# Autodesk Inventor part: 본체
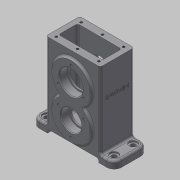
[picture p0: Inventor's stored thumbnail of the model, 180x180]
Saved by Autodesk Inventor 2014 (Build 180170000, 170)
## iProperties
Created: 2020-03
Part Number: 본체
Material: 일반
Document SubType Name: Modeling
Designer: mduedu
Density: 1 g/cm^3
Appearance: 기본값
Author: mduedu
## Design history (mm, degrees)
sketch "스케치1"
  geometry: L1 (-56, 0)-(56, 0); L2 (56, 0)-(56, 10); L3 (-56, 10)-(-56, 0); L4 (37, 10)-(37, 114); L5 (37, 114)-(-37, 114); L6 (-37, 114)-(-37, 10); L7 (56, 10)-(37, 10); L8 (-37, 10)-(-56, 10); L9 (0, 0)-(0, 114); 1 further point
  constraints: 18 end point, 5 parallel, 2 midpoint, 2 vertical, 1 coincident, 1 horizontal, 1 perpendicular
  dimensions: "d0" = 112 distance of L1.start L1.end; "d2" = 10 distance of L1.end L2.end; "d3" = 114 distance between parallel lines of L5 L1; "d4" = 74 distance between parallel lines of L4 L6
extrude "돌출1" new body sketch "스케치1" stored distance "d5" = 46; taper "d6" = 0 deg
sketch "스케치2"
  geometry: L1 (56, 0)-(-56, 0) reference; C1 r 26 at (0, 34); C2 r 26 at (0, 79); 1 further point
  constraints: 2 centre point, 2 vertical alignment, 1 equal radius
  dimensions: "d7" = 52 diameter of C2; "d9" = 34 distance from line of C1.centre L1; "d10" = 45 distance of C2.centre C1.centre
extrude "돌출2" join sketch "스케치2" stored distance "d11" = 52; taper "d12" = 0 deg
fillet "모깎기1" dims "d13" = 3
fillet "모깎기2" dims "d14" = 3
fillet "모깎기3" dims "d15" = 10
fillet "모깎기4" dims "d16" = 3
fillet "모깎기5" dims "d17" = 3
sketch "스케치3"
  geometry: L1 (-30, 114)-(30, 114); L2 (30, 114)-(30, 13); L3 (30, 13)-(-30, 13); L4 (-30, 13)-(-30, 114); L5 (-34, 114)-(34, 114) reference; L6 (46, 0)-(-46, 0) reference; 2 further points
  constraints: 8 end point, 2 parallel, 1 collinear, 1 horizontal, 1 midpoint, 1 perpendicular, 1 vertical alignment
  dimensions: "d18" = 60 distance between parallel lines of L2 L4; "d20" = 13 distance between parallel lines of L3 L6
extrude "돌출3" cut sketch "스케치3" stored distance "d21" = 26; taper "d22" = 0 deg
fillet "모깎기6" dims "d23" = 3
fillet "모깎기7" dims "d24" = 3
sketch "스케치4"
  geometry: L1 (-35, 0)-(35, 0); L2 (35, 0)-(35, 5); L3 (35, 5)-(-35, 5); L4 (-35, 5)-(-35, 0); 2 further points
  constraints: 8 end point, 2 parallel, 1 coincident, 1 horizontal, 1 midpoint, 1 perpendicular
  dimensions: "d25" = 70 distance of L1.start L1.end; "d27" = 5 distance of L1.end L2.end
extrude "돌출4" cut sketch "스케치4" stored distance "d28" = 26; taper "d29" = 0 deg
fillet "모깎기8" dims "d30" = 3
sketch "스케치5"
  geometry: A1 r 10 centre (-86, 33) between (-86, 43) and (-96, 33) reference; A2 r 10 centre (-86, 7) between (-96, 7) and (-86, -3) reference; A3 r 10 centre (6, 7) between (6, -3) and (16, 7) reference; A4 r 10 centre (6, 33) between (16, 33) and (6, 43) reference; 5 further points
  constraints: 4 coincident
hole "구멍1" sketch "스케치5" at (-86, 33), (-86, 7), (6, 7), (6, 33) diameter "d31" = 6.6; stored, may be unused: countersink angle "d35" = 90 deg, drill point angle "d37" = 118 deg; dims "d32" = 6, "d33" = 11, "d34" = 2, "d36" = 8
sketch "스케치6"
  geometry: A1 r 26 centre (0, 34) between (-16.403, 54.172) and (16.403, 54.172) reference; A2 r 3 centre (18.296, 56.5) between (16.403, 58.828) and (16.403, 54.172) reference; A3 r 26 centre (0, 79) between (16.403, 58.828) and (-16.403, 58.828) reference; A4 r 3 centre (-18.296, 56.5) between (-16.403, 54.172) and (-16.403, 58.828) reference; 2 further points
  constraints: 1 coincident
hole "구멍2" sketch "스케치6" at (0, 79) diameter "d38" = 28; stored, may be unused: countersink angle "d42" = 90 deg, drill point angle "d44" = 118 deg; dims "d39" = 6, "d40" = 32, "d41" = 11, "d43" = 8
sketch "스케치7"
  geometry: C1 r 16 at (0, 79) reference; A1 r 26 centre (0, 34) between (-16.403, 54.172) and (16.403, 54.172) reference; A2 r 3 centre (18.296, 56.5) between (16.403, 58.828) and (16.403, 54.172) reference; A3 r 26 centre (0, 79) between (16.403, 58.828) and (-16.403, 58.828) reference; A4 r 3 centre (-18.296, 56.5) between (-16.403, 54.172) and (-16.403, 58.828) reference; 2 further points
  constraints: 1 coincident
hole "구멍3" sketch "스케치7" at (0, 34) diameter "d45" = 24; stored, may be unused: countersink angle "d49" = 90 deg, drill point angle "d51" = 118 deg; dims "d46" = 6, "d47" = 28, "d48" = 11, "d50" = 8
sketch "스케치8"
  geometry: C1 r 14 at (0, 34) reference; A1 r 26 centre (0, 34) between (-16.403, 54.172) and (16.403, 54.172) reference; A2 r 3 centre (18.296, 56.5) between (16.403, 58.828) and (16.403, 54.172) reference; A3 r 26 centre (0, 79) between (16.403, 58.828) and (-16.403, 58.828) reference; A4 r 3 centre (-18.296, 56.5) between (-16.403, 54.172) and (-16.403, 58.828) reference; 2 further points
  constraints: 1 coincident
hole "구멍4" sketch "스케치8" at (0, 79) diameter "d52" = 24; stored, may be unused: countersink angle "d56" = 90 deg, drill point angle "d58" = 118 deg; dims "d53" = 6, "d54" = 28, "d55" = 11, "d57" = 8
sketch "스케치9" dims "d59" = 40
  geometry: C1 r 14 at (0, 34) reference; C2 r 16 at (0, 79) reference; A1 r 26 centre (0, 34) between (-16.403, 54.172) and (16.403, 54.172) reference; A2 r 3 centre (18.296, 56.5) between (16.403, 58.828) and (16.403, 54.172) reference; A3 r 26 centre (0, 79) between (16.403, 58.828) and (-16.403, 58.828) reference; A4 r 3 centre (-18.296, 56.5) between (-16.403, 54.172) and (-16.403, 58.828) reference; 3 further points
  constraints: 2 vertical alignment, 1 coincident, 2 other
hole "구멍5" sketch "스케치9" at (0, 99) diameter "d61" = 3.242; stored, may be unused: countersink angle "d65" = 90 deg, drill point angle "d67" = 118 deg; dims "d62" = 8, "d63" = 28, "d64" = 11, "d66" = 10
sketch "스케치10" dims "d71" = 40
  geometry: C1 r 1.621 at (17.321, 69) reference; C2 r 1.621 at (-17.321, 69) reference; C3 r 1.621 at (0, 99) reference; C4 r 14 at (0, 34) reference; C5 r 16 at (0, 79) reference; A1 r 26 centre (0, 34) between (-16.403, 54.172) and (16.403, 54.172) reference; A2 r 3 centre (18.296, 56.5) between (16.403, 58.828) and (16.403, 54.172) reference; A3 r 26 centre (0, 79) between (16.403, 58.828) and (-16.403, 58.828) reference; A4 r 3 centre (-18.296, 56.5) between (-16.403, 54.172) and (-16.403, 58.828) reference; 3 further points
  constraints: 2 vertical alignment, 1 coincident, 2 other
hole "구멍6" sketch "스케치10" at (0, 14) diameter "d72" = 3.242; stored, may be unused: countersink angle "d76" = 90 deg, drill point angle "d78" = 118 deg; dims "d73" = 8, "d74" = 28, "d75" = 11, "d77" = 10
sketch "스케치11"
  geometry: L1 (5, 6)-(63, 6); L2 (63, 6)-(63, 40); L3 (63, 40)-(5, 40); L4 (5, 40)-(5, 6); L5 (5, 6)-(63, 40); L6 (63, 6)-(5, 40); 7 further points
  constraints: 12 end point, 4 coincident, 4 midpoint, 2 parallel, 1 horizontal, 1 perpendicular
  dimensions: "d82" = 58 distance of L3.end L2.end; "d83" = 34 distance of L2.end L1.end
hole "구멍7" sketch "스케치11" at (5, 40), (63, 40), (63, 6), (5, 6), (34, 6), (34, 40) diameter "d84" = 3.242; stored, may be unused: countersink angle "d88" = 90 deg, drill point angle "d90" = 118 deg; dims "d85" = 8, "d86" = 28, "d87" = 11, "d89" = 10
fillet "모깎기9" dims "d91" = 0.3
chamfer "모따기1" distance "d92" = 1; stored, may be unused: second distance "d93" = 2, angle "d94" = 45 deg
sketch "스케치12"
  geometry: 2 further points
  constraints: 1 coincident
hole "구멍8" sketch "스케치12" at (0, -23) diameter "d95" = 4.917; stored, may be unused: countersink angle "d99" = 90 deg, drill point angle "d101" = 118 deg; dims "d96" = 8, "d97" = 12, "d98" = 1, "d100" = 10
sketch "스케치13"
  geometry: L1 (33, -13)-(7, -13) reference; L2 (40, 101)-(0, 101) reference; 3 further points
  constraints: 1 midpoint, 1 vertical alignment, 1 other
  dimensions: "d102" = 40 distance from line of point (20, 61) L2
feature "엠보싱1" sketch "스케치13" dims "d0" = 112, "d2" = 10, "d3" = 114, "d4" = 74, "d13" = 3, "d103" = 0.5, "d104" = 0
node "솔리드1"
mirror "대칭1"
pattern_circular "원형 패턴1" dims angle "d69" = 360 deg
pattern_circular "원형 패턴2" dims angle "d80" = 360 deg
mirror "대칭2"
node "투영된 루프1"
node "투영된 루프2"
node "투영된 루프3"
node "투영된 루프4"
node "투영된 루프5"
